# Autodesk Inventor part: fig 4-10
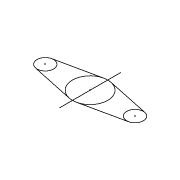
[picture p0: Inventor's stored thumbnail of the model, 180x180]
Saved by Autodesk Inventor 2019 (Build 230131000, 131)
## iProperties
Created: 2005-02
Part Number: fig 4-10
Document SubType Name: Modeling
Designer: CADCIM
Manufacturer: Standard
Standards Organization: Custom
Density: 1 g/cm^3
Material: Generic
Appearance: Default
Author: CADCIM
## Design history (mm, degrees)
sketch "Sketch1"
  geometry: L1 (-33.874, 5.844)-(-2.722, 12.469); L2 (-33.884, -5.902)-(-2.745, -12.585); L3 (-0.057, 22.288)-(-0.057, -22.318); L4 (33.759, 5.844)-(2.608, 12.469); L5 (33.77, -5.902)-(2.63, -12.585); A1 r 12.81 centre (-0.057, -0.06) between (-2.722, 12.469) and (-2.745, -12.585); A2 r 6.006 centre (-32.624, -0.03) between (-33.874, 5.844) and (-33.884, -5.902); A3 r 6.006 centre (32.51, -0.03) between (33.759, 5.844) and (33.77, -5.902)
  constraints: 10 end point, 6 point on circle, 5 symmetric about line, 4 tangent, 3 centre point, 1 vertical, 2 other
